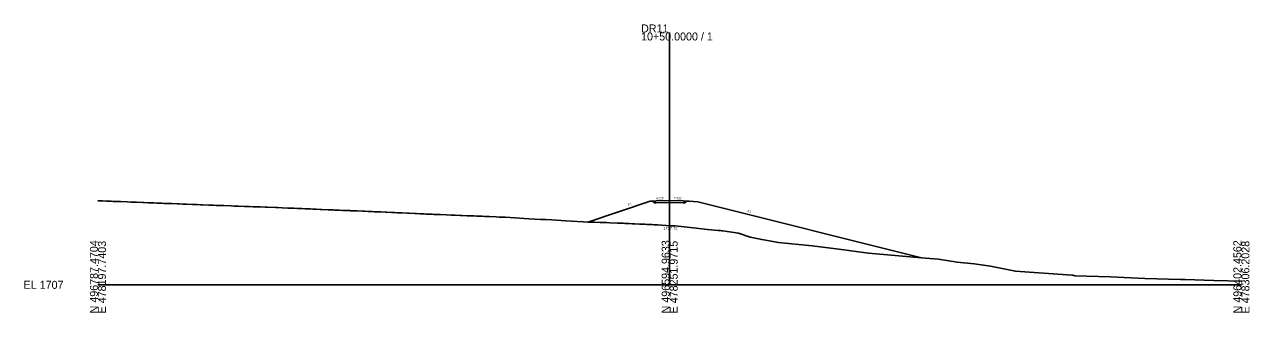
# Model space of a CAD drawing. Extents: x -26 to 478350, y -10 to 496623.
# Drawn here: x -25.7 to 402.8, y 490.3 to 591.1 of the extents above; entities that cross this region are included whole.
import ezdxf

# ---------------------------------------------------------------- set-up
doc = ezdxf.new("R2010")
doc.units = 0
for name, color, linetype in [('Exist Cross Section Cell', 7, 'Continuous'), ('Exist XS Center Line Elevation Label', 7, 'Continuous'), ('Exist XS Ground Line', 7, 'Continuous'), ('Prop XS Dump Level', 7, 'Continuous'), ('Prop XS Earthwork Shape', 7, 'Continuous'), ('Prop XS Finish Grade', 7, 'Continuous'), ('Prop XS Finish Grade Earthwork', 7, 'Continuous'), ('Prop XS Finish Grade Pavement', 7, 'Continuous'), ('Prop XS Hydro Fill Slope Data', 7, 'Continuous'), ('Prop XS Pvmt Edge Slope', 7, 'Continuous'), ('Prop XS SE Text', 7, 'Continuous'), ('Prop XS Shoulder Borrow Shape', 7, 'Continuous'), ('Prop XS Side Slope Text', 7, 'Continuous'), ('Prop XS Subgrade Earthwork', 7, 'Continuous'), ('Scratch_Level_5', 7, 'Continuous')]:
    doc.layers.add(name, color=color, linetype=linetype)

msp = doc.modelspace()

# ---------------------------------------------------------------- linework, layer by layer
at = {"layer": 'Exist Cross Section Cell'}
for p, q in [((200, 500), (200, 588.35)), ((0, 500), (200, 500)), ((200, 500), (400, 500))]:
    msp.add_line(p, q, dxfattribs=at)
at = {"layer": 'Exist XS Ground Line'}
msp.add_lwpolyline([(0, 529.45), (0.7, 529.42), (1.65, 529.38), (3.02, 529.32), (4.63, 529.26), (5.29, 529.23), (6.86, 529.17), (7.9, 529.13), (10.2, 529.04), (11.54, 528.98), (12.8, 528.93), (13.5, 528.9), (15.54, 528.82), (16.03, 528.8), (17.55, 528.74), (17.98, 528.72), (19.6, 528.66), (20.59, 528.62), (22.34, 528.55), (23.18, 528.52), (23.65, 528.51), (25.77, 528.43), (27.71, 528.35), (28.37, 528.32), (29.75, 528.27), (30.97, 528.22), (33.13, 528.14), (33.56, 528.12), (34.67, 528.08), (35.83, 528.04), (36.16, 528.03), (36.75, 528.01), (38.76, 527.93), (40.38, 527.87), (41.36, 527.83), (41.9, 527.81), (44.01, 527.73), (46.55, 527.63), (47.64, 527.59), (49.15, 527.54), (51.27, 527.46), (51.75, 527.44), (52.97, 527.39), (54.3, 527.35), (54.99, 527.32), (56.82, 527.25), (58.47, 527.19), (59.35, 527.16), (62.15, 527.06), (62.97, 527.03), (64.48, 526.96), (66.42, 526.88), (67.15, 526.85), (68.48, 526.79), (69.85, 526.74), (70.37, 526.72), (71.27, 526.68), (72.53, 526.63), (74.28, 526.55), (75.13, 526.52), (76.31, 526.46), (77.72, 526.4), (78.34, 526.38), (80.51, 526.28), (82.39, 526.21), (82.92, 526.18), (84.42, 526.12), (85.51, 526.08), (86.45, 526.04), (88.11, 525.97), (88.47, 525.95), (89.76, 525.9), (90.71, 525.85), (92.53, 525.77), (93.31, 525.74), (94.56, 525.69), (95.91, 525.63), (96.59, 525.6), (98.62, 525.51), (99.01, 525.5), (100.64, 525.43), (101.1, 525.41), (102.67, 525.33), (103.7, 525.29), (104.7, 525.25), (106.29, 525.18), (108.24, 525.09), (108.9, 525.06), (110.79, 524.97), (111.49, 524.94), (112.76, 524.88), (114.09, 524.83), (114.84, 524.79), (116.87, 524.7), (117.49, 524.68), (118.84, 524.62), (119.28, 524.6), (119.69, 524.59), (121.88, 524.5), (123.62, 524.42), (124.49, 524.39), (124.97, 524.37), (126.69, 524.29), (127.01, 524.28), (127.37, 524.27), (129.21, 524.19), (131.15, 524.12), (131.53, 524.1), (132.5, 524.07), (133.64, 524.02), (134.42, 523.99), (135.39, 523.95), (136.04, 523.92), (136.82, 523.89), (139.25, 523.78), (140.41, 523.74), (140.73, 523.72), (141.05, 523.71), (142.45, 523.65), (145.88, 523.44), (150.72, 523.13), (154.94, 522.87), (156.66, 522.83), (158.83, 522.71), (163.66, 522.43), (171.71, 521.97), (173.87, 521.9), (175.73, 521.84), (176.47, 521.82), (177.85, 521.78), (179.03, 521.74), (181.74, 521.64), (182.14, 521.62), (183.77, 521.55), (184.27, 521.52), (185.79, 521.46), (186.83, 521.41), (187.81, 521.37), (189.42, 521.29), (189.82, 521.26), (191.31, 521.19), (192.02, 521.16), (193.87, 521.08), (194.59, 521.04), (195.91, 520.98), (197.21, 520.9), (200.3, 520.7), (201.48, 520.63), (201.89, 520.6), (205.03, 520.28), (208.27, 519.93), (213.25, 519.4), (216.99, 519.04), (217.81, 518.98), (218.21, 518.95), (218.55, 518.93), (224.03, 518.04), (228.15, 516.67), (232.24, 515.82), (238.12, 514.86), (249.86, 513.63), (259.17, 512.44), (269.51, 511.04), (276.25, 510.51), (289.52, 509.34), (294.01, 508.98), (300.53, 507.92), (306.54, 507.38), (312.2, 506.51), (320.95, 504.76), (322.67, 504.7), (340.71, 503.38), (341.03, 503.34), (341.73, 503.2), (354.23, 502.79), (366.22, 502.21), (378.71, 501.88), (380.32, 501.83), (390.4, 501.54), (400, 501.24)], dxfattribs=at)
at = {"layer": 'Prop XS Dump Level'}
for p, q in [((200, 529.52), (195.23, 529.43)), ((204.77, 529.43), (200, 529.52))]:
    msp.add_line(p, q, dxfattribs=at)
at = {"layer": 'Prop XS Earthwork Shape'}
msp.add_lwpolyline([(193.21, 529.27), (171.37, 521.99), (171.71, 521.97), (173.87, 521.9), (175.73, 521.84), (176.47, 521.82), (177.85, 521.78), (179.03, 521.74), (181.74, 521.64), (182.14, 521.62), (183.77, 521.55), (184.27, 521.52), (185.79, 521.46), (186.83, 521.41), (187.81, 521.37), (189.42, 521.29), (189.82, 521.26), (191.31, 521.19), (192.02, 521.16), (193.87, 521.08), (194.59, 521.04), (195.91, 520.98), (197.21, 520.9), (200.3, 520.7), (201.48, 520.63), (201.89, 520.6), (205.03, 520.28), (208.27, 519.93), (213.25, 519.4), (216.99, 519.04), (217.81, 518.98), (218.21, 518.95), (218.55, 518.93), (224.03, 518.04), (228.15, 516.67), (232.24, 515.82), (238.12, 514.86), (249.86, 513.63), (259.17, 512.44), (269.51, 511.04), (276.25, 510.51), (288.06, 509.47), (209.82, 529.03), (206.79, 529.27), (206.04, 529.33), (205.46, 528.75), (204.77, 528.76), (200, 528.86), (195.23, 528.76), (194.54, 528.75), (193.96, 529.33)], close=True, dxfattribs=at)
at = {"layer": 'Prop XS Finish Grade'}
for p, q in [((195.23, 529.43), (193.96, 529.33)), ((204.77, 529.43), (206.04, 529.33))]:
    msp.add_line(p, q, dxfattribs=at)
at = {"layer": 'Prop XS Finish Grade Earthwork'}
for p, q in [((193.21, 529.27), (171.37, 521.99)), ((193.96, 529.33), (193.21, 529.27)), ((206.04, 529.33), (206.79, 529.27)), ((206.79, 529.27), (209.82, 529.03)), ((209.82, 529.03), (288.06, 509.47))]:
    msp.add_line(p, q, dxfattribs=at)
at = {"layer": 'Prop XS Finish Grade Pavement'}
for p, q in [((195.23, 529.43), (200, 529.52)), ((200, 529.52), (204.77, 529.43))]:
    msp.add_line(p, q, dxfattribs=at)
at = {"layer": 'Prop XS Hydro Fill Slope Data'}
msp.add_line((209.82, 529.03), (288.06, 509.47), dxfattribs=at)
at = {"layer": 'Prop XS Pvmt Edge Slope'}
for p, q in [((195.23, 529.43), (194.54, 528.75)), ((204.77, 529.43), (205.46, 528.75))]:
    msp.add_line(p, q, dxfattribs=at)
at = {"layer": 'Prop XS Shoulder Borrow Shape'}
for points in [[(195.23, 529.43), (194.54, 528.75), (193.96, 529.33)], [(205.46, 528.75), (206.04, 529.33), (204.77, 529.43)]]:
    msp.add_lwpolyline(points, close=True, dxfattribs=at)
at = {"layer": 'Prop XS Subgrade Earthwork'}
for p, q in [((194.54, 528.75), (193.96, 529.33)), ((195.23, 528.76), (194.54, 528.75)), ((200, 528.86), (195.23, 528.76)), ((204.77, 528.76), (200, 528.86)), ((204.77, 528.76), (205.46, 528.75)), ((205.46, 528.75), (206.04, 529.33))]:
    msp.add_line(p, q, dxfattribs=at)
at = {"layer": 'Scratch_Level_5'}
msp.add_lwpolyline([(0, 529.45), (0.7, 529.42), (1.65, 529.38), (3.02, 529.32), (4.63, 529.26), (5.29, 529.23), (6.86, 529.17), (7.9, 529.13), (10.2, 529.04), (11.54, 528.98), (12.8, 528.93), (13.5, 528.9), (15.54, 528.82), (16.03, 528.8), (17.55, 528.74), (17.98, 528.72), (19.6, 528.66), (20.59, 528.62), (22.34, 528.55), (23.18, 528.52), (23.65, 528.51), (25.77, 528.43), (27.71, 528.35), (28.37, 528.32), (29.75, 528.27), (30.97, 528.22), (33.13, 528.14), (33.56, 528.12), (34.67, 528.08), (35.83, 528.04), (36.16, 528.03), (36.75, 528.01), (38.76, 527.93), (40.38, 527.87), (41.36, 527.83), (41.9, 527.81), (44.01, 527.73), (46.55, 527.63), (47.64, 527.59), (49.15, 527.54), (51.27, 527.46), (51.75, 527.44), (52.97, 527.39), (54.3, 527.35), (54.99, 527.32), (56.82, 527.25), (58.47, 527.19), (59.35, 527.16), (62.15, 527.06), (62.97, 527.03), (64.48, 526.96), (66.42, 526.88), (67.15, 526.85), (68.48, 526.79), (69.85, 526.74), (70.37, 526.72), (71.27, 526.68), (72.53, 526.63), (74.28, 526.55), (75.13, 526.52), (76.31, 526.46), (77.72, 526.4), (78.34, 526.38), (80.51, 526.28), (82.39, 526.21), (82.92, 526.18), (84.42, 526.12), (85.51, 526.08), (86.45, 526.04), (88.11, 525.97), (88.47, 525.95), (89.76, 525.9), (90.71, 525.85), (92.53, 525.77), (93.31, 525.74), (94.56, 525.69), (95.91, 525.63), (96.59, 525.6), (98.62, 525.51), (99.01, 525.5), (100.64, 525.43), (101.1, 525.41), (102.67, 525.33), (103.7, 525.29), (104.7, 525.25), (106.29, 525.18), (108.24, 525.09), (108.9, 525.06), (110.79, 524.97), (111.49, 524.94), (112.76, 524.88), (114.09, 524.83), (114.84, 524.79), (116.87, 524.7), (117.49, 524.68), (118.84, 524.62), (119.28, 524.6), (119.69, 524.59), (121.88, 524.5), (123.62, 524.42), (124.49, 524.39), (124.97, 524.37), (126.69, 524.29), (127.01, 524.28), (127.37, 524.27), (129.21, 524.19), (131.15, 524.12), (131.53, 524.1), (132.5, 524.07), (133.64, 524.02), (134.42, 523.99), (135.39, 523.95), (136.04, 523.92), (136.82, 523.89), (139.25, 523.78), (140.41, 523.74), (140.73, 523.72), (141.05, 523.71), (142.45, 523.65), (145.88, 523.44), (150.72, 523.13), (154.94, 522.87), (156.66, 522.83), (158.83, 522.71), (163.66, 522.43), (171.71, 521.97), (173.87, 521.9), (175.73, 521.84), (176.47, 521.82), (177.85, 521.78), (179.03, 521.74), (181.74, 521.64), (182.14, 521.62), (183.77, 521.55), (184.27, 521.52), (185.79, 521.46), (186.83, 521.41), (187.81, 521.37), (189.42, 521.29), (189.82, 521.26), (191.31, 521.19), (192.02, 521.16), (193.87, 521.08), (194.59, 521.04), (195.91, 520.98), (197.21, 520.9), (200.3, 520.7), (201.48, 520.63), (201.89, 520.6), (205.03, 520.28), (208.27, 519.93), (213.25, 519.4), (216.99, 519.04), (217.81, 518.98), (218.21, 518.95), (218.55, 518.93), (224.03, 518.04), (228.15, 516.67), (232.24, 515.82), (238.12, 514.86), (249.86, 513.63), (259.17, 512.44), (269.51, 511.04), (276.25, 510.51), (289.52, 509.34), (294.01, 508.98), (300.53, 507.92), (306.54, 507.38), (312.2, 506.51), (320.95, 504.76), (322.67, 504.7), (340.71, 503.38), (341.03, 503.34), (341.73, 503.2), (354.23, 502.79), (366.22, 502.21), (378.71, 501.88), (380.32, 501.83), (390.4, 501.54), (400, 501.24)], dxfattribs=at)

# ---------------------------------------------------------------- texts
at = {"layer": 'Exist Cross Section Cell'}
for s, p in [('10+50.0000 / 1', (190, 585.55)), ('DR11', (190, 588.35)), ('EL 1707', (-26, 498.6))]:
    msp.add_text(s, height=2.8, dxfattribs=at).set_placement(p)
for s, p in [('N 496787.4704', (0, 490)), ('E 478197.7403', (2.8, 490)), ('N 496594.9633', (200, 490)), ('E 478251.9715', (202.8, 490)), ('N 496402.4562', (400, 490)), ('E 478306.2028', (402.8, 490))]:
    msp.add_text(s, height=2.8, rotation=90, dxfattribs=at).set_placement(p)
at = {"layer": 'Exist XS Center Line Elevation Label'}
msp.add_text('1727.72', height=1, dxfattribs=at).set_placement((197.76, 519.28))
at = {"layer": 'Prop XS SE Text'}
for rotation, p in [(1.1458, (195.28, 529.93)), (358.8542, (201.49, 530))]:
    msp.add_text('0.020', height=0.75, rotation=rotation, dxfattribs=at).set_placement(p)
at = {"layer": 'Prop XS Side Slope Text'}
for s, rotation, p in [('3:1', 18.4349, (185.42, 527.68)), ('4:1', 345.9638, (227.09, 525.55))]:
    msp.add_text(s, height=0.75, rotation=rotation, dxfattribs=at).set_placement(p)

doc.saveas('drawing.dxf')
